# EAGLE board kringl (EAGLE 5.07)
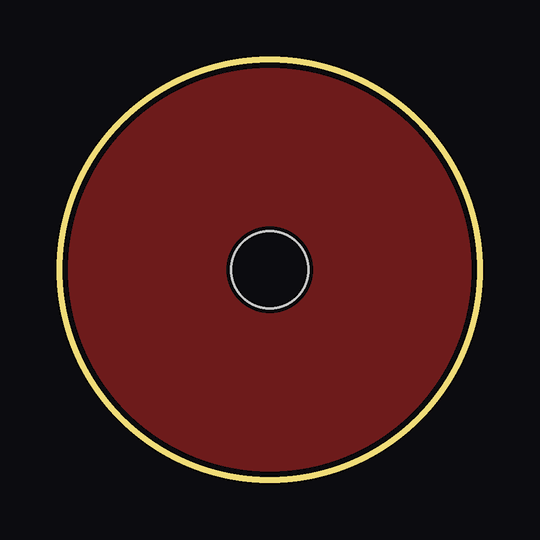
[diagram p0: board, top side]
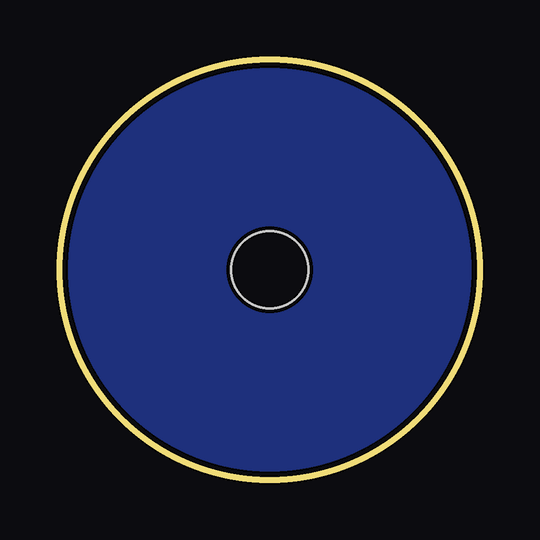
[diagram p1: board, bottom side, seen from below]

Size 17.5 x 17.5 mm. Coordinates in mm from the lower left corner, seen from the top.
Outline: circle at 8.75,8.75 radius 8.75
Copper layers (1*16): Top 0.035mm / dielectric 1.5mm / Bottom 0.035mm
Design rules "default *": minimum track width 10mil, minimum drill 20mil, track to track 8mil, track to pad 8mil, pad to pad 8mil, via to via 8mil, smd to smd 8mil, copper to edge 8mil, drill to drill 8mil, minimum pad ring 1mil, minimum via ring 8mil, stop-mask expansion 4mil, vias tented up to drill 0mil, thermal gap 10mil
Holes 3.2 mm at 8.75,8.75

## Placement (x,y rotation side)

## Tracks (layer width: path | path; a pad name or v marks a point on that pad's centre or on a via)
N$1
  pour Top: 10.16,17.14 arc-125 15.24,3.17 arc-106 1.27,3.81 arc-111 8.89,17.78
  pour Bottom: 10.16,17.14 arc-125 15.24,3.17 arc-106 1.27,3.81 arc-111 8.89,17.78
